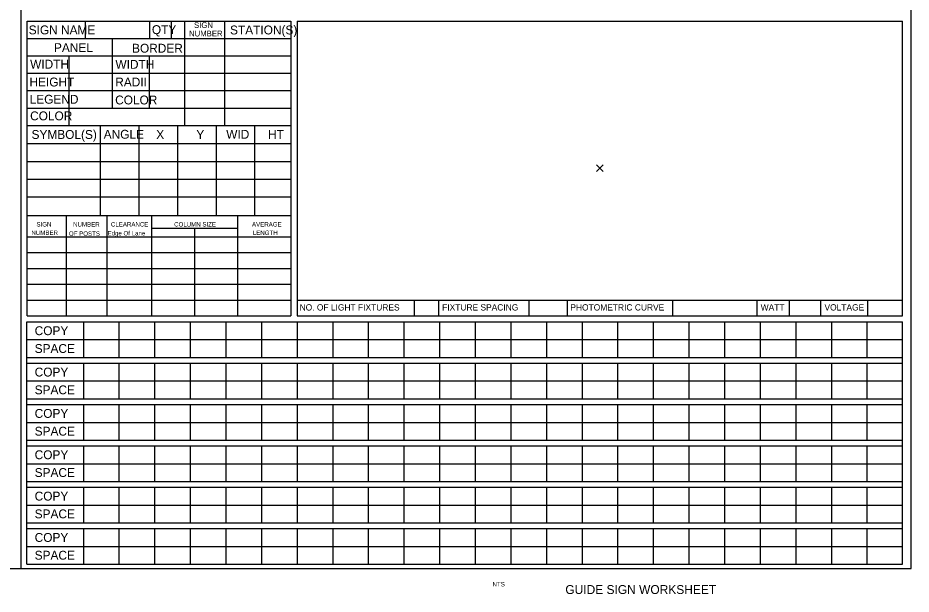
# Model space of a CAD drawing. Extents: x -998.8 to -961.2, y -2311.8 to -2287.8.
# Drawn here: x -980.09 to -961.22, y -2311.8 to -2299.62 of the extents above; entities that cross this region are included whole.
import ezdxf

# ---------------------------------------------------------------- set-up
doc = ezdxf.new("R2010")
doc.units = 0
for name, color, linetype in [('Default', 7, 'Continuous'), ('NonPlottingEle_dp', 7, 'Continuous'), ('SheetLinesMisc2_dp', 7, 'Continuous'), ('TextMinor', 7, 'Continuous'), ('TextMisc', 7, 'Continuous')]:
    doc.layers.add(name, color=color, linetype=linetype)

msp = doc.modelspace()

# ---------------------------------------------------------------- linework, layer by layer
at = {"layer": 'NonPlottingEle_dp'}
for p, q in [((-967.865, -2302.727), (-967.719, -2302.873)), ((-967.865, -2302.873), (-967.719, -2302.727))]:
    msp.add_line(p, q, dxfattribs=at)
at = {"layer": 'SheetLinesMisc2_dp'}
for p, q in [((-980.021, -2287.849), (-980.021, -2311.261)), ((-961.216, -2311.261), (-961.216, -2287.849)), ((-979.892, -2305.92), (-979.892, -2299.689)), ((-979.892, -2299.689), (-974.316, -2299.689)), ((-978.663, -2299.689), (-978.663, -2300.057)), ((-977.307, -2299.689), (-977.307, -2300.057)), ((-976.844, -2299.689), (-976.844, -2300.057)), ((-976.568, -2299.689), (-976.568, -2301.897)), ((-975.72, -2299.689), (-975.72, -2301.897)), ((-974.316, -2299.689), (-974.316, -2305.92)), ((-974.188, -2299.689), (-961.396, -2299.689)), ((-974.188, -2299.689), (-974.188, -2305.911)), ((-961.396, -2305.911), (-961.396, -2299.689)), ((-979.892, -2300.057), (-974.316, -2300.057)), ((-978.09, -2300.057), (-978.09, -2301.533)), ((-979.892, -2300.425), (-974.316, -2300.425)), ((-979.011, -2300.425), (-979.011, -2301.897)), ((-977.312, -2300.429), (-977.312, -2301.533)), ((-979.892, -2300.793), (-974.316, -2300.793)), ((-979.892, -2301.161), (-974.316, -2301.161)), ((-979.892, -2301.529), (-977.824, -2301.529)), ((-978.09, -2301.533), (-976.568, -2301.533)), ((-976.568, -2301.529), (-974.316, -2301.529)), ((-979.892, -2301.897), (-974.316, -2301.897)), ((-978.344, -2301.905), (-978.344, -2303.784)), ((-977.529, -2301.905), (-977.529, -2303.784)), ((-976.714, -2301.905), (-976.714, -2303.784)), ((-975.899, -2301.905), (-975.899, -2303.784)), ((-975.084, -2301.905), (-975.084, -2303.784)), ((-979.891, -2302.281), (-974.316, -2302.281)), ((-979.891, -2302.656), (-974.316, -2302.656)), ((-979.891, -2303.032), (-974.316, -2303.032)), ((-979.891, -2303.408), (-974.316, -2303.408)), ((-979.892, -2303.802), (-974.316, -2303.802)), ((-979.065, -2303.802), (-979.065, -2305.92)), ((-978.209, -2303.802), (-978.209, -2305.92)), ((-977.265, -2303.802), (-977.265, -2305.92)), ((-975.446, -2303.802), (-975.446, -2305.92)), ((-977.265, -2304.071), (-975.448, -2304.071)), ((-976.352, -2304.071), (-976.352, -2305.92)), ((-979.892, -2304.251), (-974.316, -2304.251)), ((-979.892, -2304.585), (-974.316, -2304.585)), ((-979.892, -2304.918), (-974.316, -2304.918)), ((-979.892, -2305.252), (-974.316, -2305.252)), ((-979.892, -2305.586), (-974.316, -2305.586)), ((-974.188, -2305.586), (-961.396, -2305.586)), ((-971.717, -2305.586), (-971.717, -2305.92)), ((-971.199, -2305.586), (-971.199, -2305.92)), ((-969.295, -2305.586), (-969.295, -2305.92)), ((-968.484, -2305.586), (-968.484, -2305.92)), ((-966.257, -2305.586), (-966.257, -2305.92)), ((-964.479, -2305.586), (-964.479, -2305.92)), ((-963.793, -2305.586), (-963.793, -2305.92)), ((-963.131, -2305.586), (-963.131, -2305.92)), ((-962.135, -2305.586), (-962.135, -2305.92)), ((-979.892, -2305.92), (-974.316, -2305.92)), ((-974.188, -2305.911), (-974.188, -2305.919)), ((-974.188, -2305.92), (-961.396, -2305.92)), ((-961.396, -2305.919), (-961.396, -2305.911)), ((-979.893, -2306.048), (-961.396, -2306.048)), ((-979.893, -2311.17), (-979.893, -2306.048)), ((-978.702, -2306.048), (-978.702, -2306.8)), ((-977.949, -2306.048), (-977.949, -2306.8)), ((-977.197, -2306.048), (-977.197, -2306.8)), ((-976.445, -2306.048), (-976.445, -2306.8)), ((-975.692, -2306.048), (-975.692, -2306.8)), ((-974.94, -2306.048), (-974.94, -2306.8)), ((-974.188, -2306.048), (-974.188, -2306.8)), ((-973.435, -2306.048), (-973.435, -2306.8)), ((-972.683, -2306.048), (-972.683, -2306.8)), ((-971.93, -2306.048), (-971.93, -2306.8)), ((-971.178, -2306.048), (-971.178, -2306.8)), ((-970.425, -2306.048), (-970.425, -2306.8)), ((-969.673, -2306.048), (-969.673, -2306.8)), ((-968.921, -2306.048), (-968.921, -2306.8)), ((-968.168, -2306.048), (-968.168, -2306.8)), ((-967.416, -2306.048), (-967.416, -2306.8)), ((-966.663, -2306.048), (-966.663, -2306.8)), ((-965.911, -2306.048), (-965.911, -2306.8)), ((-965.158, -2306.048), (-965.158, -2306.8)), ((-964.406, -2306.048), (-964.406, -2306.8)), ((-963.653, -2306.048), (-963.653, -2306.8)), ((-962.901, -2306.048), (-962.901, -2306.8)), ((-962.149, -2306.048), (-962.149, -2306.8)), ((-961.396, -2311.17), (-961.396, -2306.048)), ((-979.893, -2306.424), (-961.396, -2306.424)), ((-979.893, -2306.8), (-961.396, -2306.8)), ((-979.893, -2306.922), (-961.396, -2306.922)), ((-978.702, -2306.922), (-978.702, -2307.674)), ((-977.949, -2306.922), (-977.949, -2307.674)), ((-977.197, -2306.922), (-977.197, -2307.674)), ((-976.445, -2306.922), (-976.445, -2307.674)), ((-975.692, -2306.922), (-975.692, -2307.674)), ((-974.94, -2306.922), (-974.94, -2307.674)), ((-974.188, -2306.922), (-974.188, -2307.674)), ((-973.435, -2306.922), (-973.435, -2307.674)), ((-972.683, -2306.922), (-972.683, -2307.674)), ((-971.93, -2306.922), (-971.93, -2307.674)), ((-971.178, -2306.922), (-971.178, -2307.674)), ((-970.425, -2306.922), (-970.425, -2307.674)), ((-969.673, -2306.922), (-969.673, -2307.674)), ((-968.921, -2306.922), (-968.921, -2307.674)), ((-968.168, -2306.922), (-968.168, -2307.674)), ((-967.416, -2306.922), (-967.416, -2307.674)), ((-966.663, -2306.922), (-966.663, -2307.674)), ((-965.911, -2306.922), (-965.911, -2307.674)), ((-965.158, -2306.922), (-965.158, -2307.674)), ((-964.406, -2306.922), (-964.406, -2307.674)), ((-963.653, -2306.922), (-963.653, -2307.674)), ((-962.901, -2306.922), (-962.901, -2307.674)), ((-962.149, -2306.922), (-962.149, -2307.674)), ((-979.893, -2307.298), (-961.396, -2307.298)), ((-979.893, -2307.674), (-961.396, -2307.674)), ((-979.893, -2307.796), (-961.396, -2307.796)), ((-978.702, -2307.796), (-978.702, -2308.548)), ((-977.949, -2307.796), (-977.949, -2308.548)), ((-977.197, -2307.796), (-977.197, -2308.548)), ((-976.445, -2307.796), (-976.445, -2308.548)), ((-975.692, -2307.796), (-975.692, -2308.548)), ((-974.94, -2307.796), (-974.94, -2308.548)), ((-974.188, -2307.796), (-974.188, -2308.548)), ((-973.435, -2307.796), (-973.435, -2308.548)), ((-972.683, -2307.796), (-972.683, -2308.548)), ((-971.93, -2307.796), (-971.93, -2308.548)), ((-971.178, -2307.796), (-971.178, -2308.548)), ((-970.425, -2307.796), (-970.425, -2308.548)), ((-969.673, -2307.796), (-969.673, -2308.548)), ((-968.921, -2307.796), (-968.921, -2308.548)), ((-968.168, -2307.796), (-968.168, -2308.548)), ((-967.416, -2307.796), (-967.416, -2308.548)), ((-966.663, -2307.796), (-966.663, -2308.548)), ((-965.911, -2307.796), (-965.911, -2308.548)), ((-965.158, -2307.796), (-965.158, -2308.548)), ((-964.406, -2307.796), (-964.406, -2308.548)), ((-963.653, -2307.796), (-963.653, -2308.548)), ((-962.901, -2307.796), (-962.901, -2308.548)), ((-962.149, -2307.796), (-962.149, -2308.548)), ((-979.893, -2308.172), (-961.396, -2308.172)), ((-979.893, -2308.548), (-961.396, -2308.548)), ((-979.893, -2308.67), (-961.396, -2308.67)), ((-978.702, -2308.67), (-978.702, -2309.422)), ((-977.949, -2308.67), (-977.949, -2309.422)), ((-977.197, -2308.67), (-977.197, -2309.422)), ((-976.445, -2308.67), (-976.445, -2309.422)), ((-975.692, -2308.67), (-975.692, -2309.422)), ((-974.94, -2308.67), (-974.94, -2309.422)), ((-974.188, -2308.67), (-974.188, -2309.422)), ((-973.435, -2308.67), (-973.435, -2309.422)), ((-972.683, -2308.67), (-972.683, -2309.422)), ((-971.93, -2308.67), (-971.93, -2309.422)), ((-971.178, -2308.67), (-971.178, -2309.422)), ((-970.425, -2308.67), (-970.425, -2309.422)), ((-969.673, -2308.67), (-969.673, -2309.422)), ((-968.921, -2308.67), (-968.921, -2309.422)), ((-968.168, -2308.67), (-968.168, -2309.422)), ((-967.416, -2308.67), (-967.416, -2309.422)), ((-966.663, -2308.67), (-966.663, -2309.422)), ((-965.911, -2308.67), (-965.911, -2309.422)), ((-965.158, -2308.67), (-965.158, -2309.422)), ((-964.406, -2308.67), (-964.406, -2309.422)), ((-963.653, -2308.67), (-963.653, -2309.422)), ((-962.901, -2308.67), (-962.901, -2309.422)), ((-962.149, -2308.67), (-962.149, -2309.422)), ((-979.893, -2309.046), (-961.396, -2309.046)), ((-979.893, -2309.422), (-961.396, -2309.422)), ((-979.893, -2309.544), (-961.396, -2309.544)), ((-978.702, -2309.544), (-978.702, -2310.296)), ((-977.949, -2309.544), (-977.949, -2310.296)), ((-977.197, -2309.544), (-977.197, -2310.296)), ((-976.445, -2309.544), (-976.445, -2310.296)), ((-975.692, -2309.544), (-975.692, -2310.296)), ((-974.94, -2309.544), (-974.94, -2310.296)), ((-974.188, -2309.544), (-974.188, -2310.296)), ((-973.435, -2309.544), (-973.435, -2310.296)), ((-972.683, -2309.544), (-972.683, -2310.296)), ((-971.93, -2309.544), (-971.93, -2310.296)), ((-971.178, -2309.544), (-971.178, -2310.296)), ((-970.425, -2309.544), (-970.425, -2310.296)), ((-969.673, -2309.544), (-969.673, -2310.296)), ((-968.921, -2309.544), (-968.921, -2310.296)), ((-968.168, -2309.544), (-968.168, -2310.296)), ((-967.416, -2309.544), (-967.416, -2310.296)), ((-966.663, -2309.544), (-966.663, -2310.296)), ((-965.911, -2309.544), (-965.911, -2310.296)), ((-965.158, -2309.544), (-965.158, -2310.296)), ((-964.406, -2309.544), (-964.406, -2310.296)), ((-963.653, -2309.544), (-963.653, -2310.296)), ((-962.901, -2309.544), (-962.901, -2310.296)), ((-962.149, -2309.544), (-962.149, -2310.296)), ((-979.893, -2309.92), (-961.396, -2309.92)), ((-979.893, -2310.296), (-961.396, -2310.296)), ((-979.893, -2310.418), (-961.396, -2310.418)), ((-978.702, -2310.418), (-978.702, -2311.17)), ((-977.949, -2310.418), (-977.949, -2311.17)), ((-977.197, -2310.418), (-977.197, -2311.17)), ((-976.445, -2310.418), (-976.445, -2311.17)), ((-975.692, -2310.418), (-975.692, -2311.17)), ((-974.94, -2310.418), (-974.94, -2311.17)), ((-974.188, -2310.418), (-974.188, -2311.17)), ((-973.435, -2310.418), (-973.435, -2311.17)), ((-972.683, -2310.418), (-972.683, -2311.17)), ((-971.93, -2310.418), (-971.93, -2311.17)), ((-971.178, -2310.418), (-971.178, -2311.17)), ((-970.425, -2310.418), (-970.425, -2311.17)), ((-969.673, -2310.418), (-969.673, -2311.17)), ((-968.921, -2310.418), (-968.921, -2311.17)), ((-968.168, -2310.418), (-968.168, -2311.17)), ((-967.416, -2310.418), (-967.416, -2311.17)), ((-966.663, -2310.418), (-966.663, -2311.17)), ((-965.911, -2310.418), (-965.911, -2311.17)), ((-965.158, -2310.418), (-965.158, -2311.17)), ((-964.406, -2310.418), (-964.406, -2311.17)), ((-963.653, -2310.418), (-963.653, -2311.17)), ((-962.901, -2310.418), (-962.901, -2311.17)), ((-962.149, -2310.418), (-962.149, -2311.17)), ((-979.893, -2310.794), (-961.396, -2310.794)), ((-979.893, -2311.17), (-961.396, -2311.17)), ((-998.826, -2311.261), (-961.216, -2311.261))]:
    msp.add_line(p, q, dxfattribs=at)

# ---------------------------------------------------------------- texts
at = {"layer": 'Default'}
msp.add_text('  GUIDE SIGN WORKSHEET  ', height=0.18887, dxfattribs=at).set_placement((-968.661, -2311.801))
at = {"layer": 'TextMinor'}
for s, height, p in [('SIGN', 0.1225, (-976.364, -2299.837)), ('SIGN NAME', 0.1875, (-979.856, -2299.971)), ('QTY', 0.1875, (-977.254, -2299.965)), ('NUMBER', 0.1225, (-976.47, -2300.015)), ('STATION(S)', 0.1875, (-975.603, -2299.972)), ('PANEL', 0.1875, (-979.322, -2300.345)), ('BORDER', 0.1875, (-977.673, -2300.358)), ('WIDTH', 0.1875, (-979.826, -2300.695)), ('WIDTH', 0.1875, (-978.024, -2300.699)), ('HEIGHT', 0.1875, (-979.84, -2301.072)), ('RADII', 0.1875, (-978.028, -2301.072)), ('LEGEND', 0.1875, (-979.836, -2301.437)), ('COLOR', 0.1875, (-978.03, -2301.452)), ('COLOR', 0.1875, (-979.826, -2301.788)), ('SYMBOL(S)', 0.1875, (-979.796, -2302.181)), ('ANGLE', 0.1875, (-978.272, -2302.177)), ('X', 0.187, (-977.162, -2302.181)), ('Y', 0.187, (-976.315, -2302.181)), ('WID', 0.1875, (-975.684, -2302.177)), ('HT', 0.1875, (-974.801, -2302.181)), ('SIGN', 0.0937, (-979.693, -2304.033)), ('NUMBER', 0.0937, (-978.918, -2304.034)), ('CLEARANCE', 0.0937, (-978.119, -2304.033)), ('COLUMN SIZE', 0.09374, (-976.784, -2304.033)), ('AVERAGE', 0.0937, (-975.139, -2304.033)), ('NUMBER', 0.0937, (-979.799, -2304.211)), ('OF POSTS', 0.0937, (-979.006, -2304.229)), ('Edge Of Lane', 0.09374, (-978.192, -2304.222)), ('LENGTH', 0.0937, (-975.122, -2304.211)), ('NO. OF LIGHT FIXTURES', 0.13286, (-974.134, -2305.808)), ('FIXTURE SPACING', 0.13286, (-971.123, -2305.808)), ('PHOTOMETRIC CURVE', 0.13286, (-968.415, -2305.808)), ('WATT', 0.1329, (-964.394, -2305.808)), ('VOLTAGE', 0.1329, (-963.047, -2305.808)), ('COPY', 0.1875, (-979.73, -2306.329)), ('SPACE', 0.1875, (-979.73, -2306.705)), ('COPY', 0.1875, (-979.73, -2307.203)), ('SPACE', 0.1875, (-979.73, -2307.579)), ('COPY', 0.1875, (-979.73, -2308.077)), ('SPACE', 0.1875, (-979.73, -2308.453)), ('COPY', 0.1875, (-979.73, -2308.951)), ('SPACE', 0.1875, (-979.73, -2309.327)), ('COPY', 0.1875, (-979.73, -2309.825)), ('SPACE', 0.1875, (-979.73, -2310.201)), ('COPY', 0.1875, (-979.73, -2310.699)), ('SPACE', 0.1875, (-979.73, -2311.075))]:
    msp.add_text(s, height=height, dxfattribs=at).set_placement(p)
at = {"layer": 'TextMisc'}
msp.add_text('NTS', height=0.0944, dxfattribs=at).set_placement((-970.059, -2311.641))

doc.saveas('drawing.dxf')
